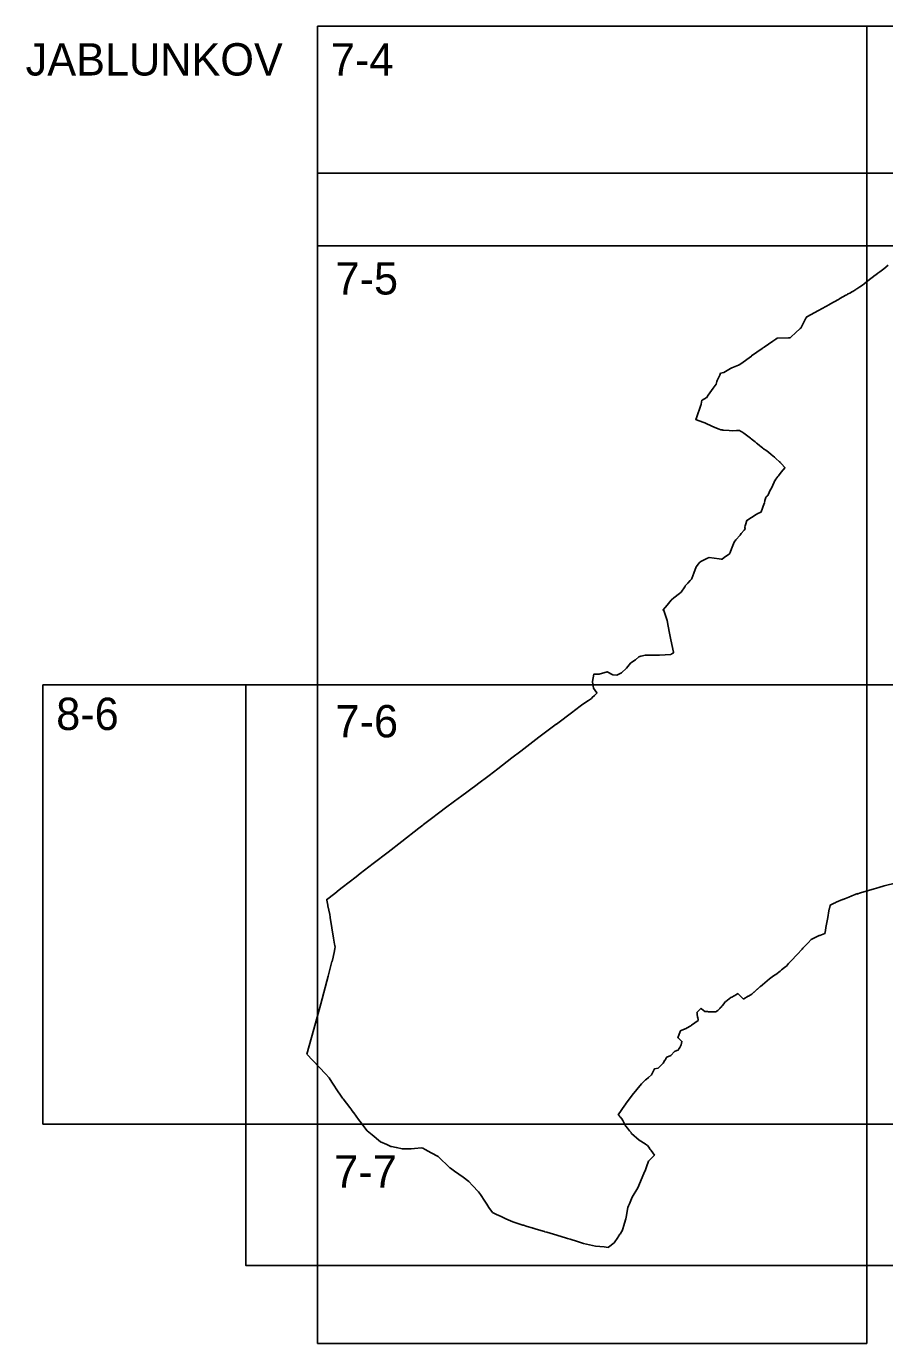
# Model space of a CAD drawing. Extents: x -447352 to -425530, y -1135906 to -1121091.
# Drawn here: x -446161.1 to -445916.9, y -1122269.2 to -1121894.2 of the extents above; entities that cross this region are included whole.
import ezdxf

# ---------------------------------------------------------------- set-up
doc = ezdxf.new("R2010")
doc.units = 0
for name, color, linetype in [('Vrstva 1', 7, 'Continuous'), ('Vrstva 10', 7, 'Continuous'), ('Vrstva 4', 7, 'Continuous')]:
    doc.layers.add(name, color=color, linetype=linetype)

msp = doc.modelspace()

# ---------------------------------------------------------------- linework, layer by layer
at = {"layer": 'Vrstva 1'}
for points in [[(-445915.92, -1121962.23), (-445917.13, -1121963.19), (-445917.13, -1121963.19), (-445918.28, -1121964.06), (-445918.85, -1121964.49), (-445919.43, -1121964.93), (-445919.59, -1121965.05), (-445921.72, -1121966.69), (-445922.79, -1121967.51), (-445923.26, -1121967.85), (-445924.02, -1121968.36), (-445924.27, -1121968.52), (-445924.86, -1121968.91), (-445924.9, -1121968.94), (-445925.11, -1121969.08), (-445926.02, -1121969.68), (-445926.03, -1121969.68), (-445926.5, -1121969.94), (-445926.65, -1121970.02), (-445926.83, -1121970.12), (-445927.29, -1121970.37), (-445927.47, -1121970.48), (-445927.63, -1121970.57), (-445927.73, -1121970.63), (-445927.97, -1121970.77), (-445929.63, -1121971.71), (-445929.8, -1121971.8), (-445930.03, -1121971.93), (-445932.5, -1121973.33), (-445932.62, -1121973.4), (-445934.73, -1121974.53), (-445935.75, -1121975.08), (-445939.09, -1121976.89), (-445939.26, -1121977.19), (-445939.32, -1121977.3), (-445940.1, -1121978.76), (-445940.78, -1121980.08), (-445940.92, -1121980.21), (-445941.01, -1121980.29), (-445942.15, -1121981.33), (-445943.66, -1121982.71), (-445943.83, -1121982.86), (-445943.83, -1121982.87), (-445944.3, -1121982.88), (-445947.49, -1121982.97), (-445947.5, -1121982.97), (-445947.93, -1121983.26), (-445948.76, -1121983.83), (-445951.23, -1121985.49), (-445951.27, -1121985.51), (-445951.51, -1121985.69), (-445951.78, -1121985.89), (-445954.76, -1121988.02), (-445954.83, -1121988.07), (-445957.83, -1121990.25), (-445958.3, -1121990.59), (-445958.46, -1121990.65), (-445960.4, -1121991.37), (-445960.41, -1121991.37), (-445960.8, -1121991.61), (-445962.68, -1121992.77), (-445963.6, -1121992.98), (-445963.85, -1121993.49), (-445964.61, -1121995), (-445964.62, -1121995.01), (-445964.69, -1121995.27), (-445964.89, -1121996.11), (-445965.72, -1121997.22), (-445967.09, -1121999.17), (-445967.65, -1121999.98), (-445967.68, -1122000), (-445968.84, -1122000.64), (-445968.94, -1122000.7), (-445969.01, -1122001.09), (-445969.16, -1122001.9), (-445969.21, -1122002.09), (-445970.5, -1122005.67), (-445970.67, -1122006.15), (-445970.64, -1122006.14), (-445970.62, -1122006.13), (-445969.94, -1122006.39), (-445968.13, -1122007.05), (-445967.51, -1122007.34), (-445965.22, -1122008.42), (-445965.2, -1122008.42), (-445964.04, -1122008.89), (-445963.57, -1122009.07), (-445963.54, -1122009.08), (-445963.11, -1122009.11), (-445962.97, -1122009.12), (-445962.75, -1122009.14), (-445961.15, -1122009.24), (-445960.11, -1122009.31), (-445959.06, -1122009.28), (-445958.22, -1122009.25), (-445958.21, -1122009.25), (-445957.93, -1122009.4), (-445957.56, -1122009.66), (-445957.01, -1122010.04), (-445956.62, -1122010.32), (-445955.06, -1122011.46), (-445954.89, -1122011.58), (-445953.78, -1122012.5), (-445953.39, -1122012.82), (-445953.21, -1122012.97), (-445952.46, -1122013.58), (-445952.19, -1122013.81), (-445951.59, -1122014.3), (-445951.37, -1122014.48), (-445950.73, -1122014.9), (-445949.98, -1122015.4), (-445949.95, -1122015.42), (-445949.19, -1122016.1), (-445948.31, -1122016.88), (-445947.87, -1122017.26), (-445946.86, -1122018.15), (-445946.6, -1122018.38), (-445946.55, -1122018.43), (-445946.45, -1122018.53), (-445946.44, -1122018.54), (-445946.35, -1122018.64), (-445946.32, -1122018.67), (-445945.27, -1122019.9), (-445945.28, -1122019.91), (-445945.72, -1122020.4), (-445945.78, -1122020.47), (-445946.35, -1122021.1), (-445947.17, -1122022.16), (-445947.34, -1122022.37), (-445947.9, -1122023.09), (-445948.2, -1122023.62), (-445948.22, -1122023.66), (-445948.23, -1122023.68), (-445948.36, -1122023.96), (-445949.16, -1122025.63), (-445949.47, -1122026.27), (-445950.09, -1122027.56), (-445950.2, -1122027.8), (-445950.21, -1122027.8), (-445950.25, -1122027.83), (-445950.54, -1122028.03), (-445950.62, -1122028.07), (-445950.67, -1122028.17), (-445950.76, -1122028.37), (-445950.85, -1122028.65), (-445951.02, -1122029.21), (-445951.03, -1122029.23), (-445951.15, -1122029.73), (-445951.17, -1122029.8), (-445951.16, -1122029.86), (-445951.15, -1122029.94), (-445951.15, -1122030.01), (-445951.16, -1122030.06), (-445952.04, -1122032.39), (-445952.06, -1122032.44), (-445952.08, -1122032.48), (-445952.09, -1122032.49), (-445952.79, -1122032.79), (-445953.04, -1122032.9), (-445953.51, -1122033.14), (-445956.12, -1122034.83), (-445956.12, -1122034.83), (-445956.49, -1122036.14), (-445956.57, -1122036.4), (-445956.68, -1122036.82), (-445956.74, -1122037.03), (-445956.74, -1122037.04), (-445956.73, -1122037.04), (-445956.56, -1122037.2), (-445956.57, -1122037.21), (-445956.93, -1122037.6), (-445957.73, -1122038.6), (-445957.74, -1122038.61), (-445957.95, -1122038.86), (-445957.95, -1122038.87), (-445958.07, -1122039.02), (-445959.23, -1122040.37), (-445959.77, -1122041), (-445960.53, -1122042.95), (-445960.91, -1122043.97), (-445961.04, -1122044.32), (-445962.57, -1122045.42), (-445963.19, -1122045.86), (-445963.37, -1122045.9), (-445963.39, -1122045.9), (-445964.02, -1122045.81), (-445966.86, -1122045.39), (-445967.35, -1122045.63), (-445968.68, -1122046.27), (-445969.22, -1122046.53), (-445969.25, -1122046.56), (-445969.68, -1122046.97), (-445969.85, -1122047.19), (-445970.51, -1122048.04), (-445970.51, -1122048.05), (-445971.18, -1122049.85), (-445971.75, -1122051.35), (-445971.75, -1122051.35), (-445971.89, -1122051.57), (-445972.22, -1122051.94), (-445972.94, -1122052.74), (-445973.64, -1122053.51), (-445973.65, -1122053.53), (-445973.78, -1122053.72), (-445974.85, -1122055.29), (-445975.32, -1122055.67), (-445976.89, -1122056.93), (-445977.56, -1122057.47), (-445977.66, -1122057.55), (-445977.69, -1122057.59), (-445978.81, -1122059.02), (-445979.95, -1122060.33), (-445979.8, -1122060.5), (-445979.79, -1122060.53), (-445979.79, -1122060.54), (-445978.78, -1122063.3), (-445978.5, -1122064.96), (-445978.18, -1122066.91), (-445977.77, -1122068.87), (-445977.04, -1122072.37), (-445977, -1122072.57), (-445977.65, -1122072.91), (-445977.77, -1122072.98), (-445980.94, -1122073.24), (-445981.1, -1122073.24), (-445982.59, -1122073.21), (-445984.98, -1122073.19), (-445986.26, -1122073.46), (-445986.86, -1122073.73), (-445987.84, -1122074.53), (-445989.14, -1122075.4), (-445989.23, -1122075.51), (-445990.39, -1122076.93), (-445991.84, -1122078.27), (-445992.53, -1122078.59), (-445993.13, -1122078.87), (-445994.3, -1122078.8), (-445995.91, -1122077.95), (-445998.15, -1122078.62), (-445999.63, -1122078.59), (-446000.01, -1122080.7), (-446000.02, -1122080.72), (-446000.03, -1122080.81), (-445999.74, -1122082.62), (-445998.77, -1122083.94), (-445998.76, -1122083.96), (-445999.5, -1122084.71), (-446000.11, -1122085.27), (-446000.36, -1122085.5), (-446001.16, -1122086.13), (-446003.09, -1122087.36), (-446003.15, -1122087.4), (-446005.12, -1122088.93), (-446005.18, -1122088.97), (-446005.67, -1122089.35), (-446010.33, -1122092.81), (-446010.36, -1122092.84), (-446015.31, -1122096.6), (-446019.57, -1122099.85), (-446020.45, -1122100.51), (-446023.02, -1122102.45), (-446027.02, -1122105.58), (-446029.46, -1122107.45), (-446032.77, -1122109.98), (-446032.82, -1122110.02), (-446037.61, -1122113.53), (-446037.84, -1122113.71), (-446041.45, -1122116.39), (-446043.84, -1122118.21), (-446045.81, -1122119.69), (-446048.13, -1122121.44), (-446048.36, -1122121.61), (-446049.49, -1122122.5), (-446054.31, -1122126.3), (-446058.2, -1122129.25), (-446062.42, -1122132.5), (-446063.71, -1122133.5), (-446066.1, -1122135.38), (-446067.28, -1122136.3), (-446071.22, -1122139.35), (-446072.15, -1122140.06), (-446073.39, -1122141.02), (-446075.71, -1122142.82), (-446075.71, -1122142.82), (-446075.67, -1122143), (-446075.38, -1122144.38), (-446075.35, -1122144.54), (-446074.82, -1122147.08), (-446074.66, -1122147.81), (-446074.66, -1122147.85), (-446073.73, -1122153.73), (-446073.72, -1122153.76), (-446073.42, -1122155.49), (-446073.42, -1122155.51), (-446073.36, -1122155.88), (-446073.3, -1122156.3), (-446073.33, -1122156.67), (-446073.48, -1122157.4), (-446073.86, -1122159.19), (-446074.15, -1122160.37), (-446074.17, -1122160.42), (-446075.28, -1122164.59), (-446077.38, -1122172.47), (-446079.37, -1122179.69), (-446081.3, -1122186.79), (-446081.31, -1122186.83), (-446076.03, -1122192.43), (-446074.98, -1122193.56), (-446074.22, -1122194.78), (-446072.2, -1122197.84), (-446072.15, -1122197.91), (-446071.14, -1122199.32), (-446070.98, -1122199.53), (-446069.1, -1122202.01), (-446068.53, -1122202.75), (-446068.5, -1122202.79), (-446067.98, -1122203.51), (-446066.6, -1122205.41), (-446066.27, -1122205.86), (-446064.12, -1122208.58), (-446062.72, -1122209.8), (-446060.32, -1122211.78), (-446058.58, -1122212.53), (-446057.39, -1122213.05), (-446057.26, -1122213.1), (-446055.93, -1122213.38), (-446055.79, -1122213.41), (-446054.17, -1122213.74), (-446054.14, -1122213.74), (-446053.18, -1122213.72), (-446052.8, -1122213.72), (-446052.28, -1122213.71), (-446051.6, -1122213.7), (-446050.69, -1122213.66), (-446048.74, -1122213.5), (-446048.29, -1122213.57), (-446047.63, -1122213.92), (-446045.91, -1122214.87), (-446043.95, -1122215.97), (-446043.43, -1122216.45), (-446042.71, -1122217.13), (-446041.91, -1122217.88), (-446040.59, -1122219.18), (-446040.45, -1122219.28), (-446039.26, -1122220.13), (-446036.85, -1122221.84), (-446035.21, -1122223.02), (-446034.16, -1122224.2), (-446032.52, -1122226.02), (-446031.88, -1122226.73), (-446031.52, -1122227.32), (-446031.06, -1122228.06), (-446030.12, -1122229.53), (-446029.49, -1122230.45), (-446028.45, -1122231.89), (-446027.38, -1122232.4), (-446026, -1122233.05), (-446024.69, -1122233.66), (-446022.72, -1122234.55), (-446021.59, -1122234.9), (-446019.87, -1122235.47), (-446019.72, -1122235.52), (-446018.63, -1122235.84), (-446017.21, -1122236.26), (-446017.2, -1122236.26), (-446016.99, -1122236.32), (-446016.93, -1122236.34), (-446016.07, -1122236.6), (-446013.68, -1122237.29), (-446013.56, -1122237.33), (-446013.08, -1122237.47), (-446010.15, -1122238.34), (-446007.46, -1122239.17), (-446007.12, -1122239.27), (-446006.36, -1122239.5), (-446004.35, -1122240.12), (-446002.62, -1122240.67), (-445999.16, -1122241.41)], [(-445999.16, -1122241.41), (-445996.77, -1122241.6), (-445995.57, -1122241.83), (-445995.46, -1122241.74), (-445993.88, -1122240.47), (-445992.85, -1122238.99), (-445992.74, -1122238.84), (-445992.22, -1122238.08), (-445992.11, -1122237.91), (-445991.97, -1122237.68), (-445991.59, -1122237.05), (-445991.32, -1122236.22), (-445991.3, -1122236.15), (-445991.28, -1122236.1), (-445991.25, -1122235.99), (-445991.22, -1122235.9), (-445991.22, -1122235.89), (-445990.59, -1122233.69), (-445990.45, -1122233.17), (-445990, -1122230.42), (-445990, -1122230.42), (-445989.81, -1122229.98), (-445989.55, -1122229.36), (-445988.76, -1122227.53), (-445987.19, -1122224.88), (-445985.44, -1122220.75), (-445985.12, -1122220.11), (-445985.08, -1122219.98), (-445984.69, -1122218.88), (-445984.1, -1122217.21), (-445982.42, -1122215.5), (-445983.35, -1122214.26), (-445983.41, -1122214.17), (-445983.46, -1122214.11), (-445983.49, -1122214.07), (-445983.56, -1122213.97), (-445983.61, -1122213.89), (-445983.69, -1122213.77), (-445984.05, -1122213.25), (-445984.42, -1122212.79), (-445984.99, -1122212.42), (-445985.09, -1122212.36), (-445986.74, -1122211.29), (-445988.93, -1122209.35), (-445989.06, -1122209.18), (-445989.09, -1122209.14), (-445989.17, -1122209.04), (-445989.51, -1122208.62), (-445989.84, -1122208.21), (-445990.1, -1122207.89), (-445990.58, -1122207.3), (-445990.66, -1122207.2), (-445991.16, -1122206.24), (-445991.45, -1122205.68), (-445991.68, -1122205.25), (-445991.73, -1122205.16), (-445991.77, -1122205.11), (-445992.03, -1122204.82), (-445992.23, -1122204.59), (-445992.49, -1122204.3), (-445992.71, -1122204.05), (-445990.85, -1122201.31), (-445990.76, -1122201.19), (-445990.44, -1122200.74), (-445990.12, -1122200.3), (-445988.79, -1122198.47), (-445986.11, -1122195.21), (-445985.76, -1122194.89), (-445985.05, -1122194.19), (-445984.94, -1122194.1), (-445984.75, -1122193.96), (-445984.15, -1122193.48), (-445983.29, -1122192.64), (-445982.88, -1122191.88), (-445982.41, -1122191.01), (-445981.36, -1122190.77), (-445979.96, -1122189.34), (-445979.42, -1122188.49), (-445979.41, -1122188.48), (-445979.41, -1122188.46), (-445979.2, -1122188.13), (-445979.15, -1122188.05), (-445978.91, -1122187.66), (-445977.75, -1122187.22), (-445976.73, -1122186.04), (-445976.2, -1122185.84), (-445976.08, -1122185.79), (-445975.66, -1122185.63), (-445975.44, -1122185.24), (-445975.39, -1122185.15), (-445975.22, -1122184.85), (-445974.81, -1122184.11), (-445974.61, -1122183.2), (-445974.61, -1122183.18), (-445974.6, -1122183.17), (-445975.65, -1122182.18), (-445975.67, -1122182.17), (-445975.68, -1122182.15), (-445975.73, -1122182.11), (-445975.08, -1122180.31), (-445975.01, -1122180.11), (-445974.85, -1122180.05), (-445974.12, -1122179.76), (-445973.43, -1122179.49), (-445973.31, -1122179.44), (-445972.1, -1122178.73), (-445971.98, -1122178.65), (-445971.98, -1122178.65), (-445971.97, -1122178.64), (-445971.85, -1122178.57), (-445969.99, -1122177.17), (-445969.99, -1122177.13), (-445970.02, -1122176.97), (-445970.09, -1122176.49), (-445970.15, -1122176.14), (-445970.25, -1122175.52), (-445970.27, -1122175.41), (-445970.29, -1122175.28), (-445970.31, -1122175.11), (-445970.34, -1122174.97), (-445969.8, -1122174.41), (-445969.24, -1122173.84), (-445969.2, -1122173.79), (-445969.06, -1122173.89), (-445968.06, -1122174.68), (-445967.38, -1122174.69), (-445967.32, -1122174.69), (-445967.07, -1122174.7), (-445966.91, -1122174.7), (-445965.6, -1122174.72), (-445964.97, -1122174.74), (-445964.7, -1122174.58), (-445964.67, -1122174.56), (-445964.55, -1122174.49), (-445964.41, -1122174.4), (-445964.37, -1122174.37), (-445963.83, -1122173.77), (-445963.72, -1122173.65), (-445963.63, -1122173.55), (-445963.46, -1122173.37), (-445963.38, -1122173.28), (-445963.27, -1122173.16), (-445963.24, -1122173.12), (-445963.21, -1122173.09), (-445963.16, -1122173.03), (-445963.07, -1122172.92), (-445962.67, -1122172.42), (-445962.46, -1122172.16), (-445962.21, -1122171.84), (-445962.1, -1122171.76), (-445960.64, -1122170.69), (-445960.43, -1122170.56), (-445959.07, -1122169.79), (-445958.67, -1122169.56), (-445958.67, -1122169.56), (-445958.53, -1122169.71), (-445957.82, -1122170.42), (-445957.45, -1122170.8), (-445957.27, -1122170.97), (-445957.12, -1122171.12), (-445957.03, -1122171.08), (-445955.75, -1122170.31), (-445955.66, -1122170.26), (-445954.73, -1122169.7), (-445954.69, -1122169.67), (-445954.36, -1122169.38), (-445954.31, -1122169.34), (-445954.14, -1122169.19), (-445954.13, -1122169.18), (-445954.13, -1122169.18), (-445954.09, -1122169.14), (-445954.05, -1122169.1), (-445953.16, -1122168.29), (-445953.14, -1122168.28), (-445952.55, -1122167.74), (-445952.44, -1122167.65), (-445952.33, -1122167.55), (-445952.33, -1122167.55), (-445952.32, -1122167.55), (-445952.32, -1122167.55), (-445952.32, -1122167.54), (-445952.31, -1122167.54), (-445952.3, -1122167.53), (-445952.3, -1122167.53), (-445952.29, -1122167.52), (-445952.29, -1122167.52), (-445952.28, -1122167.52), (-445952.28, -1122167.52), (-445951.7, -1122167.03), (-445949.71, -1122165.35), (-445948.51, -1122164.5), (-445948.39, -1122164.42), (-445948.34, -1122164.38), (-445948.32, -1122164.37), (-445948.27, -1122164.34), (-445947.91, -1122164.07), (-445946.67, -1122163.13), (-445946.49, -1122162.99), (-445946.28, -1122162.83), (-445946.26, -1122162.81), (-445945.38, -1122162.14), (-445945.03, -1122161.87), (-445944.98, -1122161.81), (-445944.89, -1122161.71), (-445944.25, -1122161.03), (-445943.35, -1122160.05), (-445941.99, -1122158.64), (-445941.77, -1122158.41), (-445941.52, -1122158.13), (-445940.68, -1122157.18), (-445940.39, -1122156.86), (-445940.19, -1122156.65), (-445939.9, -1122156.33), (-445938.72, -1122155.14), (-445937.79, -1122154.12), (-445935.73, -1122153.11), (-445935.57, -1122153.06), (-445935.37, -1122152.98), (-445933.93, -1122152.49), (-445933.78, -1122151.62), (-445933.62, -1122150.75), (-445933.2, -1122148.38), (-445933.12, -1122147.91), (-445932.79, -1122146.03), (-445932.59, -1122145.15), (-445932.56, -1122145.03), (-445932.51, -1122144.84), (-445932.5, -1122144.8), (-445932.48, -1122144.73), (-445932.47, -1122144.69), (-445932.46, -1122144.64), (-445932.45, -1122144.6), (-445932.44, -1122144.58), (-445932.38, -1122144.37), (-445931.3, -1122143.83), (-445931.01, -1122143.69), (-445930.99, -1122143.68), (-445930.74, -1122143.55), (-445930.69, -1122143.53), (-445928.92, -1122142.81), (-445928.89, -1122142.8), (-445928.86, -1122142.78), (-445928.06, -1122142.47), (-445927.1, -1122142.07), (-445926.29, -1122141.73), (-445925.35, -1122141.34), (-445925.27, -1122141.31), (-445924.66, -1122141.07), (-445924.81, -1122141.23), (-445924.57, -1122141.14), (-445924.08, -1122140.94), (-445923.55, -1122140.78), (-445921.85, -1122140.26), (-445921.26, -1122140.09), (-445920.81, -1122139.97), (-445919.92, -1122139.72), (-445918.61, -1122139.34), (-445917.07, -1122138.88), (-445913.53, -1122138.01)]]:
    msp.add_lwpolyline(points, dxfattribs=at)
at = {"layer": 'Vrstva 10'}
msp.add_lwpolyline([(-445765.77, -1121936.02), (-445765.77, -1122247), (-446098.64, -1122247), (-446098.64, -1122081.7), (-446078.27, -1122081.7), (-446078.27, -1121956.7), (-446078.27, -1121936.02), (-445765.77, -1121936.02)], dxfattribs=at)
at = {"layer": 'Vrstva 4'}
for p, q in [((-446078.27, -1121894.2), (-445765.77, -1121894.2)), ((-446156.4, -1122081.7), (-446156.4, -1122206.7)), ((-446078.27, -1122269.2), (-445922.02, -1122269.2))]:
    msp.add_line(p, q, dxfattribs=at)
for points in [[(-445922.02, -1121894.2), (-445922.02, -1121956.7), (-446078.27, -1121956.7), (-446078.27, -1121894.2)], [(-445765.77, -1121894.2), (-445765.77, -1121956.7), (-445922.02, -1121956.7), (-445922.02, -1121894.2)], [(-446156.4, -1122081.7), (-446078.27, -1122081.7), (-446078.27, -1122206.7), (-446156.4, -1122206.7)], [(-446078.27, -1122269.2), (-446078.27, -1122206.7), (-445922.02, -1122206.7), (-445922.02, -1122269.2)]]:
    msp.add_lwpolyline(points, dxfattribs=at)
for points in [[(-445922.02, -1121956.7), (-445922.02, -1122081.7), (-446078.27, -1122081.7), (-446078.27, -1121956.7)], [(-445765.77, -1121956.7), (-445765.77, -1122081.7), (-445922.02, -1122081.7), (-445922.02, -1121956.7)], [(-445922.02, -1122081.7), (-445922.02, -1122206.7), (-446078.27, -1122206.7), (-446078.27, -1122081.7)], [(-445765.77, -1122081.7), (-445765.77, -1122206.7), (-445922.02, -1122206.7), (-445922.02, -1122081.7)]]:
    msp.add_lwpolyline(points, close=True, dxfattribs=at)

# ---------------------------------------------------------------- texts
at = {"layer": 'Vrstva 1'}
for s, p in [('JABLUNKOV', (-446161.31, -1121908.2)), ('7-4', (-446074.46, -1121908.2)), ('7-5', (-446073.15, -1121970.54)), ('8-6', (-446152.62, -1122094.51)), ('7-6', (-446073.15, -1122096.61)), ('7-7', (-446073.51, -1122224.78))]:
    msp.add_text(s, height=9.2, dxfattribs=at).set_placement(p)

doc.saveas('drawing.dxf')
